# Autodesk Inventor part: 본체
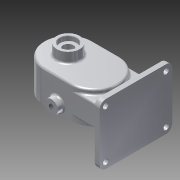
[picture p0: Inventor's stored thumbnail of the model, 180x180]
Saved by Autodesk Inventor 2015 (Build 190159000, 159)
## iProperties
Created: 2020-09
Part Number: 본체
Material: 알루미늄 6061
Document SubType Name: Modeling
Designer: LINEART-SSD.D4.16.07
Density: 2.7 g/cm^3
Appearance: 알루미늄 - 평지
Mass: 1439.71 g
Surface Area: 785.637 cm^2
Volume: 533.225 cm^3
Author: LINEART-SSD.D4.16.07
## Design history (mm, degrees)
sketch "스케치1"
  geometry: L1 (0, 0)-(-44, 0); L2 (0, 40)-(-44, 40); L3 (-44, -40)-(0, -40); A1 r 40 centre (0, 0) between (0, -40) and (0, 40); A2 r 40 centre (-44, 0) between (-44, 40) and (-44, -40); 1 further point
  constraints: 8 end point, 4 point on circle, 4 tangent, 2 centre point, 1 horizontal, 1 midpoint, 1 parallel
  dimensions: "d0" = 80 diameter of A2; "d4" = 44 distance of L1.start L1.end
extrude "돌출1" new body sketch "스케치1" distance "d2" = 53; taper "d3" = 0 deg
sketch "스케치2"
  geometry: L1 (44, 0)-(0, 0); L2 (44, -24)-(0, -24); L3 (0, 24)-(44, 24); L4 (0, 40)-(44, 40) reference; A1 r 24 centre (44, 0) between (44, -24) and (44, 24); A2 r 24 centre (0, 0) between (0, 24) and (0, -24); A3 r 40 centre (0, 0) between (0, 40) and (0, -40) reference; A4 r 40 centre (44, 0) between (44, -40) and (44, 40) reference; 2 further points
  constraints: 8 end point, 4 point on circle, 4 tangent, 2 centre point, 1 horizontal, 1 midpoint, 1 parallel
  dimensions: "d5" = 24 radius of A1; "d6" = 44 distance of L1.start L1.end; "d7" = 40 distance from line of point (22, 0) L4; "d8" = 22 distance of point (22, 0) A4.centre
extrude "돌출2" cut sketch "스케치2" distance "d9" = 29; taper "d10" = 0 deg
sketch "스케치4"
  geometry: C1 r 19 at (-44, 0); A1 r 40 centre (-44, 0) between (-44, 40) and (-44, -40) reference; 1 further point
  constraints: 1 centre point, 1 coincident
  dimensions: "d22" = 38 diameter of C1
extrude "돌출3" join sketch "스케치4" distance "d23" = 17; taper "d24" = 0 deg
sketch "스케치5"
  geometry: L1 (44, 0)-(44, 0) reference; L2 (44, 0)-(44, 29) reference; L3 (44, 29)-(44, 29) reference; L4 (44, 0)-(44, 29) reference; L5 (63, 70)-(25, 70) reference; L6 (68, 29)-(44, 29) reference; L7 (44, 0)-(44, 70); L8 (56.5, 29)-(56.5, 44); L9 (56.5, 44)-(52.5, 44); L10 (52.5, 44)-(52.5, 62); L11 (52.5, 62)-(58, 62); L12 (58, 62)-(58, 69.3); L13 (58, 69.3)-(58.404, 70); L14 (56.5, 29)-(44, 29); L15 (58.404, 70)-(44, 70); L16 (44, 29)-(44, 70); 1 further point
  constraints: 20 end point, 6 perpendicular, 2 point on line, 1 collinear, 1 midpoint, 1 vertical
  dimensions: "d25" = 15 distance of L8.start L8.end; "d26" = 0.7 vertical distance of L12.end L13.end; "d27" = 30 deg angle of L12 L13; "d28" = 28 diameter of L12 L7; "d29" = 7.3 distance of L11.end L12.end; "d30" = 17 diameter of L10 L7; "d31" = 25 diameter of L8 L7
revolve "회전1" sketch "스케치5" stored, may be unused: angle "d32" = 90 deg
sketch "스케치6"
  geometry: C1 r 12.5 at (0, 0); 1 further point
  constraints: 1 centre point, 1 coincident
  dimensions: "d33" = 25 diameter of C1
extrude "돌출4" cut sketch "스케치6" distance "d34" = 15; taper "d35" = 0 deg
node "작업 평면2"
  node "작업 평면1"
sketch "스케치7"
  geometry: L1 (19, 70)-(-19, 70) reference; L2 (0, 70)-(60, 70); L3 (60, 70)-(60, -30); L4 (60, -30)-(-60, -30); L5 (-60, -30)-(-60, 70); L6 (-60, 70)-(0, 70); 1 further point
  constraints: 10 end point, 2 perpendicular, 1 collinear, 1 horizontal, 1 midpoint, 1 vertical
  dimensions: "d38" = 60 distance of L2.start L2.end; "d39" = 100 distance of L2.end L3.end; "d40" = 120 distance of L3.end L4.end
extrude "돌출5" join sketch "스케치7" distance "d41" = 10; taper "d42" = 0 deg
node "작업 평면3"
sketch "스케치8"
  geometry: L1 (0, 40)-(-44, 40) reference; L2 (-44, -40)-(0, -40) reference; L3 (58, -60)-(58, 60) reference; L4 (0, 40)-(58, 40); L5 (0, -40)-(58, -40); L6 (58, 40)-(58, -40); A1 r 40 centre (0, 0) between (0, -40) and (0, 40) reference; A2 r 40 centre (0, 0) between (0, -40) and (0, 40); 1 further point
  constraints: 6 end point, 3 tangent, 2 perpendicular, 2 point on circle, 2 point on line, 1 centre point, 1 collinear
extrude "돌출6" join sketch "스케치8" stored distance "d44" = 37; taper "d45" = 0 deg
fillet "모깎기1" dims "d46" = 3
fillet "모깎기2" dims "d47" = 3
sketch "스케치9"
  geometry: L1 (0, 0)-(44, 0) reference; C1 r 11 at (22, 14)
  constraints: 1 centre point
  dimensions: "d48" = 22 diameter of C1; "d49" = 14 distance from line of L1 C1.centre; "d50" = 22 horizontal distance of C1.centre L1.start
extrude "돌출7" join sketch "스케치9" distance "d51" = 10; taper "d52" = 0 deg
sketch "스케치10"
  geometry: C1 r 11 at (22, -14) reference; C2 r 11 at (22, -14); 1 further point
  constraints: 1 centre point, 1 coincident, 1 concentric
extrude "돌출8" join sketch "스케치10" distance "d53" = 10; taper "d54" = 0 deg
sketch "스케치11"
  geometry: C1 r 11 at (0, 0) reference; 2 further points
  constraints: 1 coincident
hole "구멍1" sketch "스케치11" at (0, 0) diameter "d55" = 8.376; stored, may be unused: countersink angle "d59" = 90 deg, drill point angle "d61" = 0 deg; dims "d56" = 20, "d57" = 4, "d58" = 2, "d60" = 27.3
sketch "스케치12"
  geometry: C1 r 11 at (0, 0) reference; 2 further points
  constraints: 1 coincident
hole "구멍2" sketch "스케치12" at (0, 0) diameter "d62" = 8.376; stored, may be unused: countersink angle "d66" = 90 deg, drill point angle "d68" = 0 deg; dims "d63" = 20, "d64" = 4, "d65" = 2, "d67" = 27.3
sketch "스케치13"
  geometry: C1 r 8.5 at (44, 0) reference; 2 further points
  constraints: 1 horizontal alignment
  dimensions: "d69" = 31 distance of C1.centre point (75, 0)
hole "구멍3" sketch "스케치13" at (75, 0) diameter "d70" = 4.134; stored, may be unused: countersink angle "d74" = 90 deg, drill point angle "d76" = 118 deg; dims "d71" = 10, "d72" = 4, "d73" = 2, "d75" = 12
sketch "스케치14"
  geometry: C1 r 8.5 at (44, 0) reference; 3 further points
  constraints: 2 vertical alignment
  dimensions: "d77" = 31 distance of point (44, 31) C1.centre; "d78" = 31 distance of C1.centre point (44, -31)
hole "구멍4" sketch "스케치14" at (44, 31), (44, -31) diameter "d79" = 4.134; stored, may be unused: countersink angle "d83" = 90 deg, drill point angle "d85" = 118 deg; dims "d80" = 10, "d81" = 4, "d82" = 2, "d84" = 12
fillet "모깎기3" dims "d92" = 3
chamfer "모따기1" distance "d93" = 1; stored, may be unused: second distance "d94" = 2, angle "d95" = 45 deg
fillet "모깎기4" dims "d96" = 0.5
fillet "모깎기5" dims "d97" = 3
fillet "모깎기6" dims "d98" = 10
sketch "스케치15"
  geometry: A1 r 10 centre (-20, -50) between (-30, -50) and (-20, -60) reference; 2 further points
  constraints: 1 coincident
hole "구멍5" sketch "스케치15" at (-20, -50) diameter "d99" = 9; stored, may be unused: countersink angle "d103" = 90 deg, drill point angle "d105" = 0 deg; dims "d100" = 10, "d101" = 4, "d102" = 2, "d104" = 12
sketch "스케치16"
  geometry: A1 r 10 centre (60, -50) between (60, -60) and (70, -50) reference; A2 r 10 centre (60, 50) between (70, 50) and (60, 60) reference; A3 r 10 centre (-20, 50) between (-20, 60) and (-30, 50) reference; 4 further points
  constraints: 3 coincident
hole "구멍6" sketch "스케치16" at (60, -50), (60, 50), (-20, 50) diameter "d112" = 9; stored, may be unused: countersink angle "d116" = 90 deg, drill point angle "d118" = 0 deg; dims "d113" = 10, "d114" = 4, "d115" = 2, "d117" = 12
sketch "스케치17"
  geometry: L1 (60, 60)-(-20, 60) reference; L2 (-30, 50)-(-30, -50) reference; 2 further points
  constraints: 1 other
  dimensions: "d119" = 60 distance from line of L1 point (-18, 0); "d120" = 12 distance from line of L2 point (-18, 0)
feature "엠보싱1" sketch "스케치17" dims "d121" = 0.5, "d122" = 0
fillet "모깎기7" dims "d123" = 3
node "솔리드1"
pattern_linear "직사각형 패턴1" dims "d88" = 44
pattern_linear "직사각형 패턴2" dims "d91" = 106
node "투영된 루프1"
other parameters: "d36" = -22, "d43" = 26.5
